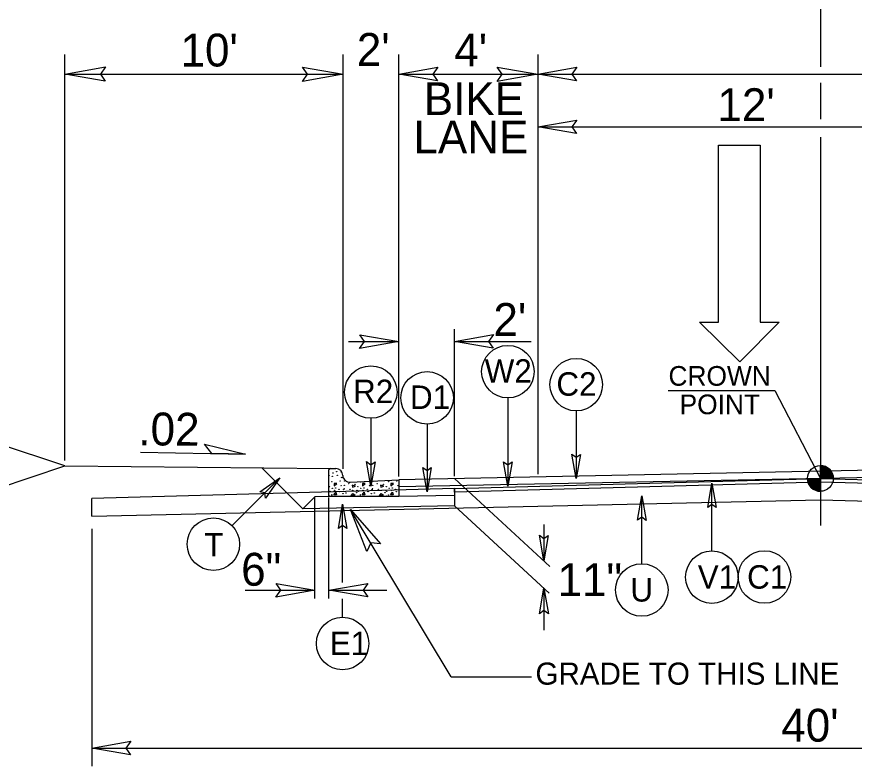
# Model space of a CAD drawing. Extents: x 957297 to 961629, y 830661 to 840840.
# Drawn here: x 959115.8 to 959314.5, y 836659.8 to 836837.7 of the extents above; entities that cross this region are included whole.
import ezdxf

# ---------------------------------------------------------------- set-up
doc = ezdxf.new("R2010")
doc.units = 0
for name, color, linetype in [('Default', 7, 'Continuous'), ('Old_Level_1', 7, 'Continuous'), ('Old_Level_11', 7, 'Continuous'), ('Old_Level_3', 7, 'Continuous'), ('Prop CMT Pvmt Milling', 7, 'Continuous'), ('Prop Dimension Text', 7, 'Continuous'), ('Prop Lane Arrow CELL', 7, 'Continuous'), ('Typical ID Circle CELL', 7, 'Continuous'), ('Typical Terminator CELL', 7, 'Continuous'), ('Typical Text Grade Point CELL', 7, 'Continuous'), ('Typical Text ID Circle CELL', 7, 'Continuous')]:
    doc.layers.add(name, color=color, linetype=linetype)

# ---------------------------------------------------------------- blocks, each defined once
blk = doc.blocks.new('Lane Arrow Through')
at = {"layer": 'Prop Lane Arrow CELL'}
for p, q in [((-3.15, 1.6), (-3.15, 3.1)), ((-3.15, 3.1), (0, 0)), ((-17.15, 1.6), (-3.15, 1.6)), ((-17.15, -1.7), (-17.15, 1.6)), ((0, 0), (-3.15, -3.2)), ((-3.15, -1.7), (-17.15, -1.7)), ((-3.15, -3.2), (-3.15, -1.7))]:
    blk.add_line(p, q, dxfattribs=at)

msp = doc.modelspace()

# ---------------------------------------------------------------- linework, layer by layer
at = {"layer": 'Default'}
for p, q in [((959306.49, 836870.09), (959306.49, 836825.83)), ((959306.49, 836822), (959306.49, 836813.4)), ((959306.49, 836809.11), (959306.49, 836716.94))]:
    msp.add_line(p, q, dxfattribs=at)
at = {"layer": 'Old_Level_1'}
for p, q in [((959127.17, 836732.41), (959127.17, 836828.73)), ((959193.21, 836730.42), (959193.21, 836828.73)), ((959206.42, 836728.57), (959206.42, 836828.73)), ((959239.42, 836828.73), (959239.42, 836729.11)), ((959127.17, 836824.11), (959193.21, 836824.11)), ((959206.42, 836824.11), (959239.42, 836824.11)), ((959239.42, 836824.11), (959494.54, 836824.11)), ((959239.42, 836811.56), (959332.9, 836811.56)), ((959219.62, 836728.66), (959219.62, 836763.55)), ((959194.48, 836760.62), (959206.42, 836760.62)), ((959219.62, 836760.62), (959237.85, 836760.62)), ((959127.17, 836731.11), (959049.98, 836756.84)), ((959145.1, 836734.38), (959170.07, 836733.88)), ((959426.38, 836732.27), (959206.42, 836727.83)), ((959049.98, 836705.38), (959127.17, 836731.11)), ((959127.17, 836731.11), (959190.13, 836730.48)), ((959183.65, 836720.89), (959173.9, 836730.64)), ((959426.42, 836730.55), (959206.42, 836726.1)), ((959306.49, 836728.12), (959306.49, 836731.19)), ((959219.62, 836728.09), (959242.32, 836707.21)), ((959303.43, 836728.12), (959306.49, 836728.12)), ((959309.55, 836728.12), (959306.49, 836728.12)), ((959306.49, 836725.08), (959306.49, 836728.12)), ((959306.49, 836728.12), (959306.49, 836725.08)), ((959219.62, 836724.11), (959206.42, 836723.84)), ((959219.62, 836725.74), (959219.62, 836721.62)), ((959133.56, 836719.15), (959133.55, 836723.4)), ((959186.54, 836723.78), (959183.65, 836720.89)), ((959189.84, 836723.84), (959186.54, 836723.78)), ((959186.54, 836699.62), (959186.54, 836723.58)), ((959189.84, 836699.62), (959189.84, 836723.58)), ((959219.62, 836721.62), (959183.65, 836720.89)), ((959218.88, 836681.04), (959195, 836720.77)), ((959219.62, 836721.62), (959242.13, 836700.9)), ((959133.56, 836716.17), (959133.56, 836659.8)), ((959240.87, 836717.22), (959240.87, 836708.54)), ((959169.94, 836701.58), (959186.54, 836701.58)), ((959189.84, 836701.58), (959203.57, 836701.58)), ((959240.85, 836702.08), (959240.85, 836692.12)), ((959218.88, 836681.04), (959237.91, 836681.04)), ((959133.56, 836664.09), (959479.39, 836664.09))]:
    msp.add_line(p, q, dxfattribs=at)
for points in [[(959306.52, 836731.19), (959306.52, 836731.19), (959306.52, 836728.12)], [(959306.58, 836731.19), (959306.58, 836728.12)], [(959306.64, 836731.18), (959306.64, 836728.12)], [(959306.71, 836731.18), (959306.71, 836728.12)], [(959306.77, 836731.18), (959306.77, 836728.12)], [(959306.83, 836731.18), (959306.83, 836728.12)], [(959306.89, 836731.16), (959306.89, 836728.12)], [(959306.95, 836731.16), (959306.95, 836728.12)], [(959307, 836731.14), (959307, 836728.12)], [(959307.06, 836731.14), (959307.06, 836728.12)], [(959307.13, 836731.12), (959307.13, 836728.12)], [(959307.19, 836731.11), (959307.19, 836728.12)], [(959307.25, 836731.09), (959307.25, 836728.12)], [(959307.31, 836731.07), (959307.31, 836728.12)], [(959307.38, 836731.05), (959307.38, 836728.12)], [(959307.44, 836731.03), (959307.44, 836728.12)], [(959307.5, 836731.02), (959307.5, 836728.12)], [(959307.56, 836730.99), (959307.56, 836728.12)], [(959307.62, 836730.98), (959307.62, 836728.12)], [(959307.69, 836730.95), (959307.69, 836728.12)], [(959307.75, 836730.93), (959307.75, 836728.12)], [(959307.81, 836730.89), (959307.81, 836728.12)], [(959307.86, 836730.87), (959307.86, 836728.12)], [(959307.92, 836730.84), (959307.92, 836728.12)], [(959307.98, 836730.8), (959307.98, 836728.12)], [(959308.05, 836730.77), (959308.05, 836728.12)], [(959308.11, 836730.73), (959308.11, 836728.12)], [(959308.17, 836730.68), (959308.17, 836728.12)], [(959308.23, 836730.64), (959308.23, 836728.12)], [(959308.29, 836730.61), (959308.29, 836728.12)], [(959308.35, 836730.55), (959308.35, 836728.12)], [(959308.42, 836730.51), (959308.42, 836728.12)], [(959308.48, 836730.46), (959308.48, 836728.12)], [(959308.54, 836730.4), (959308.54, 836728.12)], [(959308.6, 836730.34), (959308.6, 836728.12)], [(959308.67, 836730.28), (959308.67, 836728.12)], [(959308.72, 836730.22), (959308.72, 836728.12)], [(959308.78, 836730.16), (959308.78, 836728.12)], [(959308.84, 836730.09), (959308.84, 836728.12)], [(959303.45, 836728.12), (959303.45, 836727.8)], [(959303.51, 836728.12), (959303.51, 836727.44)], [(959303.57, 836728.12), (959303.57, 836727.22)], [(959303.63, 836728.12), (959303.63, 836727.04)], [(959303.7, 836728.12), (959303.7, 836726.89)], [(959303.76, 836728.12), (959303.76, 836726.76)], [(959303.81, 836728.12), (959303.81, 836726.65)], [(959303.87, 836728.12), (959303.87, 836726.54)], [(959303.94, 836728.12), (959303.94, 836726.45)], [(959304, 836728.12), (959304, 836726.36)], [(959304.06, 836728.12), (959304.06, 836726.27)], [(959304.12, 836728.12), (959304.12, 836726.2)], [(959304.18, 836728.12), (959304.18, 836726.13)], [(959304.24, 836728.12), (959304.24, 836726.06)], [(959304.3, 836728.12), (959304.3, 836725.99)], [(959304.37, 836728.12), (959304.37, 836725.94)], [(959304.43, 836728.12), (959304.43, 836725.88)], [(959304.49, 836728.12), (959304.49, 836725.82)], [(959304.55, 836728.12), (959304.55, 836725.78)], [(959304.62, 836728.12), (959304.62, 836725.72)], [(959304.67, 836728.12), (959304.67, 836725.68)], [(959304.73, 836728.12), (959304.73, 836725.63)], [(959304.79, 836728.12), (959304.79, 836725.59)], [(959304.85, 836728.12), (959304.85, 836725.54)], [(959304.92, 836728.12), (959304.92, 836725.5)], [(959304.98, 836728.12), (959304.98, 836725.47)], [(959305.04, 836728.12), (959305.04, 836725.43)], [(959305.1, 836728.12), (959305.1, 836725.42)], [(959305.16, 836728.12), (959305.16, 836725.38)], [(959305.23, 836728.12), (959305.23, 836725.34)], [(959305.29, 836728.12), (959305.29, 836725.33)], [(959305.35, 836728.12), (959305.35, 836725.29)], [(959305.41, 836728.12), (959305.41, 836725.28)], [(959305.47, 836728.12), (959305.47, 836725.25)], [(959305.52, 836728.12), (959305.52, 836725.23)], [(959305.59, 836728.12), (959305.59, 836725.21)], [(959305.65, 836728.12), (959305.65, 836725.19)], [(959305.71, 836728.12), (959305.71, 836725.18)], [(959305.77, 836728.12), (959305.77, 836725.17)], [(959305.83, 836728.12), (959305.83, 836725.15)], [(959305.9, 836728.12), (959305.9, 836725.13)], [(959305.95, 836728.12), (959305.95, 836725.13)], [(959306.02, 836728.12), (959306.02, 836725.12)], [(959306.08, 836728.12), (959306.08, 836725.09)], [(959306.14, 836728.12), (959306.14, 836725.09)], [(959306.21, 836728.12), (959306.21, 836725.09)], [(959306.27, 836728.12), (959306.27, 836725.08)], [(959306.33, 836728.12), (959306.33, 836725.08)], [(959306.38, 836728.12), (959306.38, 836725.08)], [(959306.44, 836728.12), (959306.44, 836725.08), (959306.44, 836725.08)], [(959308.9, 836730), (959308.9, 836728.12)], [(959308.97, 836729.92), (959308.97, 836728.12)], [(959309.03, 836729.84), (959309.03, 836728.12)], [(959309.09, 836729.75), (959309.09, 836728.12)], [(959309.14, 836729.64), (959309.14, 836728.12)], [(959309.21, 836729.54), (959309.21, 836728.12)], [(959309.27, 836729.39), (959309.27, 836728.12)], [(959309.33, 836729.25), (959309.33, 836728.12)], [(959309.39, 836729.09), (959309.39, 836728.12)], [(959309.46, 836728.88), (959309.46, 836728.12)], [(959309.52, 836728.57), (959309.52, 836728.12)], [(959219.62, 836725.74), (959133.55, 836723.4)], [(959133.56, 836719.15), (959306.49, 836723.08)], [(959306.49, 836723.08), (959479.42, 836718.37)]]:
    msp.add_lwpolyline(points, dxfattribs=at)
msp.add_circle((959306.49, 836728.13), 3.06, dxfattribs=at)
for start, end in [(359.9905, 89.9905), (179.9905, 269.9905)]:
    msp.add_arc((959306.49, 836728.13), 3.06, start, end, dxfattribs=at)
at = {"layer": 'Old_Level_11'}
for p, q in [((959162.07, 836734.04), (959160.34, 836736.3)), ((959160.34, 836736.3), (959170.07, 836733.88)), ((959170.07, 836733.88), (959162.07, 836734.04))]:
    msp.add_line(p, q, dxfattribs=at)
for points in [[(959136.78, 836822.45), (959127.17, 836824.11), (959136.83, 836825.81), (959135.61, 836824.11)], [(959183.6, 836825.76), (959193.21, 836824.11), (959183.54, 836822.39), (959184.77, 836824.11)], [(959229.81, 836825.76), (959239.42, 836824.11), (959229.75, 836822.39), (959230.98, 836824.11)], [(959198.88, 836710.77), (959195, 836720.77), (959202.09, 836712.63), (959199.78, 836712.81)]]:
    msp.add_lwpolyline(points, close=True, dxfattribs=at)
at = {"layer": 'Old_Level_3'}
for p, q in [((959189.84, 836727.16), (959189.84, 836730.19)), ((959190.13, 836730.48), (959191.5, 836730.48)), ((959193.29, 836728.43), (959193.18, 836728.29)), ((959193.18, 836728.29), (959193.33, 836728.32)), ((959189.84, 836723.84), (959189.84, 836727.16)), ((959191.12, 836726.93), (959191.12, 836726.35)), ((959191.7, 836726.9), (959191.12, 836726.93)), ((959191.12, 836726.35), (959191.7, 836726.9)), ((959194.88, 836727.25), (959206.42, 836727.83)), ((959194.88, 836727.25), (959194.88, 836727.25)), ((959195.34, 836726.52), (959195.43, 836726.04)), ((959196.16, 836726.29), (959195.34, 836726.52)), ((959195.43, 836726.04), (959196.16, 836726.29)), ((959197.85, 836726.93), (959197.85, 836726.35)), ((959198.43, 836726.9), (959197.85, 836726.93)), ((959197.85, 836726.35), (959198.43, 836726.9)), ((959202.06, 836726.52), (959202.16, 836726.04)), ((959202.9, 836726.29), (959202.06, 836726.52)), ((959202.16, 836726.04), (959202.9, 836726.29)), ((959204.58, 836726.93), (959204.58, 836726.35)), ((959205.16, 836726.9), (959204.58, 836726.93)), ((959204.58, 836726.35), (959205.16, 836726.9)), ((959206.42, 836727.83), (959206.42, 836723.84)), ((959191.03, 836724.23), (959191.5, 836724.88)), ((959191.67, 836724.26), (959191.03, 836724.23)), ((959191.5, 836724.88), (959191.67, 836724.26)), ((959195.15, 836723.96), (959195.49, 836724.57)), ((959196.04, 836724.17), (959195.15, 836723.96)), ((959195.49, 836724.57), (959196.04, 836724.17)), ((959197.76, 836724.23), (959198.22, 836724.88)), ((959198.4, 836724.26), (959197.76, 836724.23)), ((959198.22, 836724.88), (959198.4, 836724.26)), ((959201.88, 836723.96), (959202.22, 836724.57)), ((959202.78, 836724.17), (959201.88, 836723.96)), ((959202.22, 836724.57), (959202.78, 836724.17)), ((959204.49, 836724.23), (959204.95, 836724.88)), ((959205.13, 836724.26), (959204.49, 836724.23)), ((959204.95, 836724.88), (959205.13, 836724.26)), ((959206.42, 836723.84), (959189.84, 836723.84))]:
    msp.add_line(p, q, dxfattribs=at)
for centre in [(959189.9, 836728.75), (959190.66, 836728.65), (959190.82, 836729.39), (959191.68, 836729.76), (959191.83, 836728.84), (959192.78, 836729.64), (959192.81, 836728.35), (959189.99, 836726.16), (959190.54, 836727.36), (959192.48, 836727.55), (959192.75, 836726.44), (959193.49, 836726.5), (959193.58, 836727.51), (959194.57, 836726.9), (959196.01, 836726.75), (959196.72, 836726.16), (959199.48, 836726.44), (959200.22, 836726.5), (959201.3, 836726.9), (959202.74, 836726.75), (959203.45, 836726.16), (959204, 836727.36), (959205.93, 836727.55), (959206.21, 836726.44), (959190.11, 836725.09), (959190.54, 836724.23), (959190.69, 836725.76), (959191.21, 836725.31), (959191.46, 836725.85), (959192.26, 836725.52), (959192.41, 836724.97), (959193.21, 836724.51), (959193.37, 836725.43), (959193.46, 836725.7), (959193.89, 836724.66), (959194.84, 836725.55), (959195.49, 836725.28), (959196.44, 836724.75), (959196.54, 836725.28), (959196.84, 836725.09), (959197.27, 836724.23), (959197.42, 836725.76), (959197.94, 836725.31), (959198.19, 836725.85), (959198.99, 836725.52), (959199.14, 836724.97), (959199.94, 836724.51), (959200.1, 836725.43), (959200.19, 836725.7), (959200.62, 836724.66), (959201.57, 836725.55), (959202.22, 836725.28), (959203.17, 836724.75), (959203.26, 836725.28), (959203.56, 836725.09), (959204, 836724.23), (959204.15, 836725.76), (959204.67, 836725.31), (959204.92, 836725.85), (959205.72, 836725.52), (959205.87, 836724.97), (959190.02, 836723.98), (959196.75, 836723.98), (959203.48, 836723.98)]:
    msp.add_circle(centre, 0.0432, dxfattribs=at)
for centre, radius, start, end in [((959190.13, 836730.19), 0.287, 90, 180), ((959190.02, 836730.41), 0.0432, 259.6531, 10.3469), ((959191.5, 836728.82), 1.66, 1.0734, 90), ((959194.79, 836728.89), 1.64, 181.0734, 272.8624), ((959197.27, 836727.36), 0.0432, 167.7795, 17.938), ((959200.31, 836727.51), 0.0432, 169.8374, 15.8801), ((959189.81, 836725.28), 0.0432, 330.4173, 29.5827)]:
    msp.add_arc(centre, radius, start, end, dxfattribs=at)
at = {"layer": 'Prop CMT Pvmt Milling'}
for p, q in [((959219.62, 836725.74), (959306.49, 836728.11)), ((959306.51, 836727.25), (959306.49, 836728.12)), ((959219.62, 836724.88), (959219.62, 836725.74))]:
    msp.add_line(p, q, dxfattribs=at)
for points in [[(959306.49, 836728.11), (959306.51, 836727.25), (959219.62, 836724.88)], [(959306.49, 836728.12), (959426.46, 836724.85)], [(959426.44, 836723.98), (959306.51, 836727.25)]]:
    msp.add_lwpolyline(points, dxfattribs=at)
at = {"layer": 'Typical ID Circle CELL'}
for p, q in [((959232.33, 836747.26), (959232.33, 836726.29)), ((959248.55, 836744.17), (959248.55, 836728.08)), ((959199.79, 836742.41), (959199.79, 836726.32)), ((959213.15, 836741.02), (959213.15, 836724.93)), ((959166.83, 836716.91), (959178.2, 836728.29)), ((959280.74, 836710.93), (959280.74, 836727.02)), ((959264.1, 836707.87), (959264.1, 836723.96)), ((959193.1, 836703.42), (959193.1, 836722.03)), ((959193.1, 836695.16), (959193.1, 836699.52))]:
    msp.add_line(p, q, dxfattribs=at)
for centre in [(959232.33, 836753.48), (959248.55, 836750.39), (959199.79, 836748.63), (959213.15, 836747.25), (959162.43, 836712.51), (959280.74, 836704.7), (959293.21, 836704.73), (959264.1, 836701.65), (959193.1, 836688.94)]:
    msp.add_circle(centre, 6.23, dxfattribs=at)
at = {"layer": 'Typical Terminator CELL'}
for points in [[(959215.64, 836822.52), (959206.42, 836824.11), (959215.69, 836825.74), (959214.51, 836824.11)], [(959248.64, 836822.52), (959239.42, 836824.11), (959248.69, 836825.74), (959247.51, 836824.11)], [(959248.64, 836809.98), (959239.42, 836811.56), (959248.69, 836813.2), (959247.51, 836811.56)], [(959197.19, 836762.21), (959206.42, 836760.62), (959197.14, 836758.98), (959198.32, 836760.62)], [(959228.84, 836759.04), (959219.62, 836760.62), (959228.89, 836762.26), (959227.72, 836760.62)], [(959200.79, 836732.09), (959199.79, 836726.32), (959198.77, 836732.12), (959199.79, 836731.38)], [(959233.33, 836732.05), (959232.33, 836726.29), (959231.31, 836732.08), (959232.33, 836731.35)], [(959249.54, 836733.84), (959248.55, 836728.08), (959247.52, 836733.87), (959248.55, 836733.14)], [(959214.14, 836730.7), (959213.15, 836724.93), (959212.12, 836730.73), (959213.15, 836729.99)], [(959173.42, 836724.91), (959178.2, 836728.29), (959174.83, 836723.46), (959174.62, 836724.71)], [(959279.75, 836721.25), (959280.74, 836727.02), (959281.76, 836721.22), (959280.74, 836721.96)], [(959263.11, 836718.19), (959264.1, 836723.96), (959265.13, 836718.16), (959264.1, 836718.9)], [(959192.1, 836716.27), (959193.1, 836722.03), (959194.12, 836716.23), (959193.1, 836716.97)], [(959241.91, 836714.61), (959240.87, 836708.54), (959239.79, 836714.65), (959240.87, 836713.87)], [(959177.32, 836703.17), (959186.54, 836701.58), (959177.27, 836699.94), (959178.45, 836701.58)], [(959199.07, 836699.99), (959189.84, 836701.58), (959199.12, 836703.22), (959197.94, 836701.58)], [(959239.81, 836696.01), (959240.85, 836702.08), (959241.93, 836695.98), (959240.85, 836696.76)], [(959142.78, 836662.5), (959133.56, 836664.09), (959142.83, 836665.73), (959141.65, 836664.09)]]:
    msp.add_lwpolyline(points, close=True, dxfattribs=at)
at = {"layer": 'Typical Text Grade Point CELL'}
for p, q in [((959270.38, 836749.01), (959295.71, 836749.01)), ((959295.71, 836749.01), (959306.49, 836728.12))]:
    msp.add_line(p, q, dxfattribs=at)

# ---------------------------------------------------------------- block references
at = {"layer": 'Old_Level_1', "xscale": 3, "yscale": 3, "rotation": -90.00000000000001}
msp.add_blockref('Lane Arrow Through', (959287.38, 836755.81), dxfattribs=at)

# ---------------------------------------------------------------- texts
at = {"layer": 'Old_Level_1'}
msp.add_text('GRADE TO THIS LINE', height=5.2473, dxfattribs=at).set_placement((959238.87, 836679.17))
at = {"layer": 'Old_Level_11'}
for s, p in [('CROWN', (959270.44, 836750.13)), ('POINT', (959273.08, 836743.37))]:
    msp.add_text(s, height=4.671, dxfattribs=at).set_placement(p)
at = {"layer": 'Old_Level_3'}
for s, p in [("10'", (959154.64, 836825.91)), ("2'", (959196.48, 836826.06)), ("4'", (959219.61, 836825.93)), ('BIKE', (959212.37, 836814.37)), ('LANE', (959209.92, 836805.27))]:
    msp.add_text(s, height=7.801, dxfattribs=at).set_placement(p)
msp.add_text('.02', height=7.801, rotation=359.4336, dxfattribs=at).set_placement((959144.6, 836736.01))
at = {"layer": 'Prop Dimension Text'}
for s, p in [("12'", (959282.07, 836812.94)), ("2'", (959228.9, 836761.96)), ('6"', (959169.02, 836702.66)), ('11"', (959244.12, 836700.19)), ("40'", (959297.22, 836665.64))]:
    msp.add_text(s, height=7.801, rotation=0, dxfattribs=at).set_placement(p)
at = {"layer": 'Typical Text ID Circle CELL'}
for s, height, p in [('W2', 5.572, (959226.82, 836750.85)), ('C2', 5.572, (959243.84, 836747.76)), ('R2', 5.572, (959195.59, 836746)), ('D1', 5.572, (959209.09, 836744.62)), ('V1', 5.572, (959277.39, 836701.96)), ('C1', 5.572, (959289.1, 836701.96)), ('U', 5.57, (959261.4, 836698.9)), ('E1', 5.572, (959190.06, 836686.2))]:
    msp.add_text(s, height=height, dxfattribs=at).set_placement(p)
msp.add_text('T', height=5.57, rotation=360, dxfattribs=at).set_placement((959160.28, 836709.61))

doc.saveas('drawing.dxf')
